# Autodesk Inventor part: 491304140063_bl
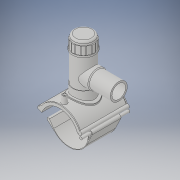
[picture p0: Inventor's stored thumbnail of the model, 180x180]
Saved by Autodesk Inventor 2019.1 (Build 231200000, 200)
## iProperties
Created: 2017-07
Part Number: 491304140063_bl
Material: Generic
Description: PLASSON TAPPING TEE SADDLE 140mm x 63mm
Document SubType Name: Modeling
Designer: KIM
Mass: 1712.7 g
Surface Area: 2671.49 cm^2
Volume: 1712.7 cm^3
Density: 1 g/cm^3
Appearance: Default
Author: KIM
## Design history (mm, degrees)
derived "491304.ipt"
feature "Solid1::491304.ipt" dims "ScaleForDerivedMember" = 10
feature "Solid2::491304.ipt" dims "ScaleForDerivedMember" = 10
feature "Solid4::491304.ipt" dims "ScaleForDerivedMember" = 10
feature "Solid5::491304.ipt" dims "ScaleForDerivedMember" = 10
tag "TaggingFeature1"
body "Solid1"
body "Solid2"
other parameters: "d1" = 101.118 [user parameter], "d2" = 273.6 [user parameter], "d3" = 35 [user parameter], "d4" = 176 [user parameter], "d5" = 0 [user parameter], "d6" = 0.1 [user parameter], "d8" = 0 [user parameter], "d40" = 84 [user parameter], "d41" = 97.65 [user parameter], "d43" = 0 [user parameter], "d45" = 0 [user parameter], "d47" = 156.159 [user parameter], "d78" = 105 [user parameter], "d79" = 15 [user parameter], "d80" = 70.4 [user parameter], "d82" = 5 deg [user parameter], "d84" = 4 [user parameter], "d85" = 14 [user parameter], "d86" = 0 [user parameter], "d87" = 3 [user parameter], "d88" = 0 [user parameter], "d97" = 3.52 [user parameter], "d98" = 0 [user parameter], "d102" = 1.4 [user parameter], "d120" = 140 deg [user parameter], "d123" = 606.708 [user parameter], "d126" = 0 [user parameter], "d153" = 176 [user parameter], "d154" = 0 [user parameter], "d159" = -7.7764 [user parameter], "d162" = 105.6 [user parameter], "d163" = 0 [user parameter], "d169" = 4.0905 [user parameter], "d172" = 0 [user parameter], "d173" = 1 [user parameter], "d176" = 20 deg [user parameter], "d177" = 9.8 [user parameter], "d180" = 0 [user parameter], "d184" = 7.84 [user parameter], "d187" = 77 [user parameter], "d188" = 15 [user parameter], "d189" = 9.8 [user parameter], "d190" = 0 [user parameter], "d191" = 105 [user parameter], "d195" = 90 deg [user parameter], "d197" = 0 [user parameter], "d199" = 0 [user parameter], "d200" = 9.8 [user parameter], "d202" = 0 [user parameter], "d203" = 195 [user parameter], "d206" = 75.6 [user parameter], "d207" = 146.25 [user parameter], "d208" = 152.1 [user parameter], "d209" = 181.35 [user parameter], "d210" = 76.86 [user parameter], "d212" = 72.45 [user parameter], "d213" = 39.15 [user parameter], "d216" = 0 [user parameter], "d217" = 14 [user parameter], "d218" = 7 [user parameter], "d219" = 1.4 [user parameter], "d224" = 0 [user parameter], "d259" = 50.4 [user parameter], "d260" = 63 [user parameter], "d263" = 171 [user parameter], "d265" = 0 [user parameter], "d267" = 13.00006 [user parameter], "d268" = 2.60001 [user parameter], "d269" = 2.60001 [user parameter], "d271" = 2.60001 [user parameter], "d273" = 0 [user parameter], "d274" = 23.56194 [user parameter], "d275" = 112 [user parameter], "d277" = 56 [user parameter], "d278" = 224 [user parameter], "d280" = 0 [user parameter], "d283" = 0 [user parameter], "d285" = 0 [user parameter], "d290" = 14 [user parameter], "d293" = 77 [user parameter], "d294" = 72.1 [user parameter], "d296" = 21 [user parameter], "d299" = 75 [user parameter], "d300" = 3 [user parameter], "d301" = 5 [user parameter], "d303" = 81.9 [user parameter], "d304" = 69.3 [user parameter], "d305" = 45 deg [user parameter], "d306" = 50.4 [user parameter], "d307" = 87.5 [user parameter], "d308" = 84 [user parameter], "d310" = 1 [user parameter], "B" = 171 [user parameter], "L" = 176 [user parameter], "d_t" = 6 [user parameter], "H2" = 195 [user parameter], "H1" = 75 [user parameter], "d_1" = 63 [user parameter]
